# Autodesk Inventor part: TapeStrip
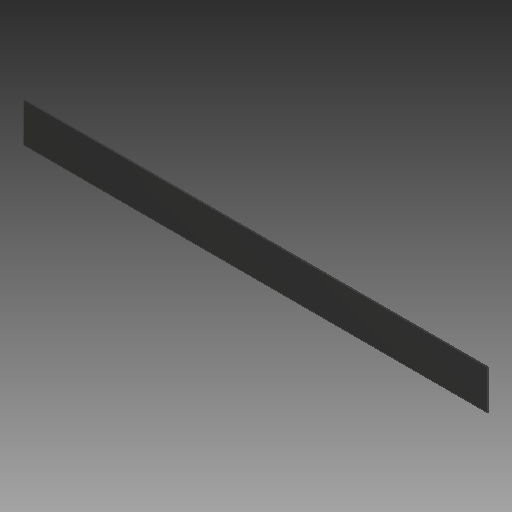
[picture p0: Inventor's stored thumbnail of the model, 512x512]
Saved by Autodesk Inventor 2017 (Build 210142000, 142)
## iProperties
Created: 2017-05
Part Number: TapeStrip
Material: Generic
Document SubType Name: Modeling
Designer: Savy
Density: 1 g/cm^3
Appearance: Default
Mass: 3.81 g
Surface Area: 155.654 cm^2
Volume: 3.81 cm^3
Author: Savy
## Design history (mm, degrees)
feature "Base1"
body "Solid1"
